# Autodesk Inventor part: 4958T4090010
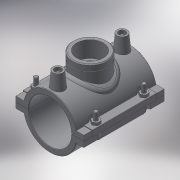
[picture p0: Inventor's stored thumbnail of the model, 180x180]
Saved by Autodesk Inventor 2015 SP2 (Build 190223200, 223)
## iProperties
Created: 2017-07
Part Number: 4958T4090010
Material: Generic
Description: PLASSON SADDLE 90X1" FEMALE BSPP
Document SubType Name: Modeling
Designer: KIM
Density: 1 g/cm^3
Appearance: Default
Author: KIM
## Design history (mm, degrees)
derived "4958T4.ipt"
feature "Solid1::4958T4.ipt"
tag "TaggingFeature1"
body "Solid1"
other parameters: "d1" = 112.5, "d2" = 126, "d3" = 22.5, "d4" = 118, "d5" = 0, "d6" = 0.1, "d8" = 0, "d19" = 6, "d20" = 6, "d21" = 70.8, "d23" = 0, "d24" = 35.4, "d26" = 0, "d27" = 3, "d28" = 3, "d29" = 3, "d30" = 24.00694, "d31" = 6, "d32" = 0, "d33" = 0, "d34" = 0.6, "d40" = 60.3, "d43" = 0, "d45" = 0, "d46" = 9, "d47" = 75, "d48" = 39.3783, "d50" = 0, "d51" = 30.291, "d52" = 24, "d53" = 0, "d54" = 24.2328, "d56" = 0, "d57" = -9, "d58" = 0.5, "d59" = 0.1, "d60" = 0, "d61" = 0.5, "d64" = 0.90873, "d67" = 0.9, "d70" = 15, "d72" = 0, "d73" = 6, "d75" = 5, "d76" = 0, "d77" = 4.5, "d78" = 74, "d79" = 15, "d80" = 47.2, "d82" = 5 deg, "d84" = 4, "d85" = 14, "d86" = 0, "d87" = 3, "d88" = 0, "d89" = 1, "d90" = 1, "d91" = 94.4, "d92" = 0, "d93" = 0.5, "d94" = 47.36842, "Rp_" = 30.291, "B_" = 126, "L_" = 118, "d_t" = 6
